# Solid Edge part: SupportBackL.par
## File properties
Author: Wojciech Szerszeń
Template: ISO Metric Part.par
Last saved by: wojci
Revision: 6
Application: Solid Edge
Username: Wojciech Szerszeń
Accuracy: 0.990
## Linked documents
SupportBack.par
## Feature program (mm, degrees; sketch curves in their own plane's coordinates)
part copy "CopiedPart_1"
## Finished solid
Body 1: solid body, 55 faces, 145 edges, 90 vertices.
  Faces by surface: plane 41, cylinder 13, spline 1
  Edges by curve: line 103, circle 23, ellipse 7, curve on surface 6, intersection 6
Bounding box of the edges (mm; curved faces can reach further): 24.000 x 36.000 x 72.500, from (-24.0001, -5, 0) to (0, 31, 72.5).
Cylindrical faces by radius (mm): R1.2295 x4, R1.6 x1, R3.25 x3, R3.5 x1, R8 x1, R10 x1, R13 x1, R40 x1
Planar faces by outward normal: +x 6, +y 4, +z 5, -x 7, -y 7, -z 5, oblique 7
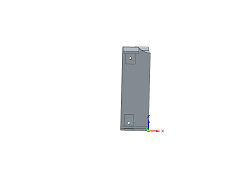
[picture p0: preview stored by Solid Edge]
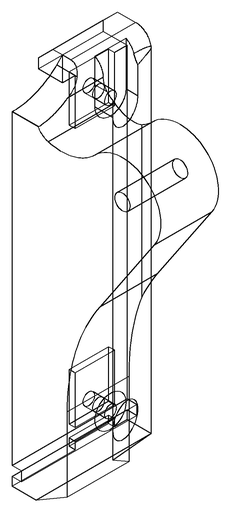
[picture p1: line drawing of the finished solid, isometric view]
